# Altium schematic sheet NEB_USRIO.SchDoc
size A4; Organization: Altium Limited; Address1: L3, 12a Rodborough Rd; Address2: Frenchs Forest; Address3: NSW; Address4: Australia 2086; DocumentNumber: 6; SheetNumber: 6; SheetTotal: 10
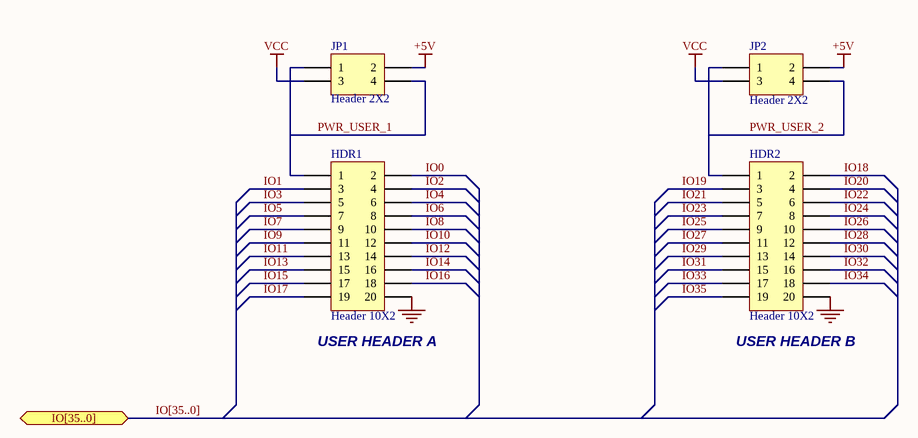
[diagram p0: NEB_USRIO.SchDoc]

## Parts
HDR1  Header 10X2  [HDR2X10]
HDR2  Header 10X2  [HDR2X10]
JP1  Header 2X2  [HDR2X2_B]
JP2  Header 2X2  [HDR2X2_B]

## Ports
IO[35..0] (bidir)

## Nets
+5V: JP1.2 JP2.2
GND: HDR1.20 HDR2.20
VCC: JP1.3 JP2.3
IO0: HDR1.2
IO1: HDR1.3
IO2: HDR1.4
IO3: HDR1.5
IO4: HDR1.6
IO5: HDR1.7
IO6: HDR1.8
IO7: HDR1.9
IO8: HDR1.10
IO9: HDR1.11
IO10: HDR1.12
IO11: HDR1.13
IO12: HDR1.14
IO13: HDR1.15
IO14: HDR1.16
IO15: HDR1.17
IO16: HDR1.18
IO17: HDR1.19
IO18: HDR2.2
IO19: HDR2.3
IO20: HDR2.4
IO21: HDR2.5
IO22: HDR2.6
IO23: HDR2.7
IO24: HDR2.8
IO25: HDR2.9
IO26: HDR2.10
IO27: HDR2.11
IO28: HDR2.12
IO29: HDR2.13
IO30: HDR2.14
IO31: HDR2.15
IO32: HDR2.16
IO33: HDR2.17
IO34: HDR2.18
IO35: HDR2.19
PWR_USER_1: HDR1.1 JP1.1 JP1.4
PWR_USER_2: HDR2.1 JP2.1 JP2.4

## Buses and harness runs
bus IO[35..0] = port IO[35..0]

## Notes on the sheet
- (near HDR1) USER HEADER A
- (near HDR2) USER HEADER B

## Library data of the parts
HDR1 HDR2 = Header 10X2: Header, 10-Pin, Dual row; Manufacturer: Generic Components; Class I: Connector; Fitted: True
JP1 JP2 = Header 2X2: Header, 2-Pin, Dual row; Manufacturer: Generic Components; Class I: Connector; Fitted: True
